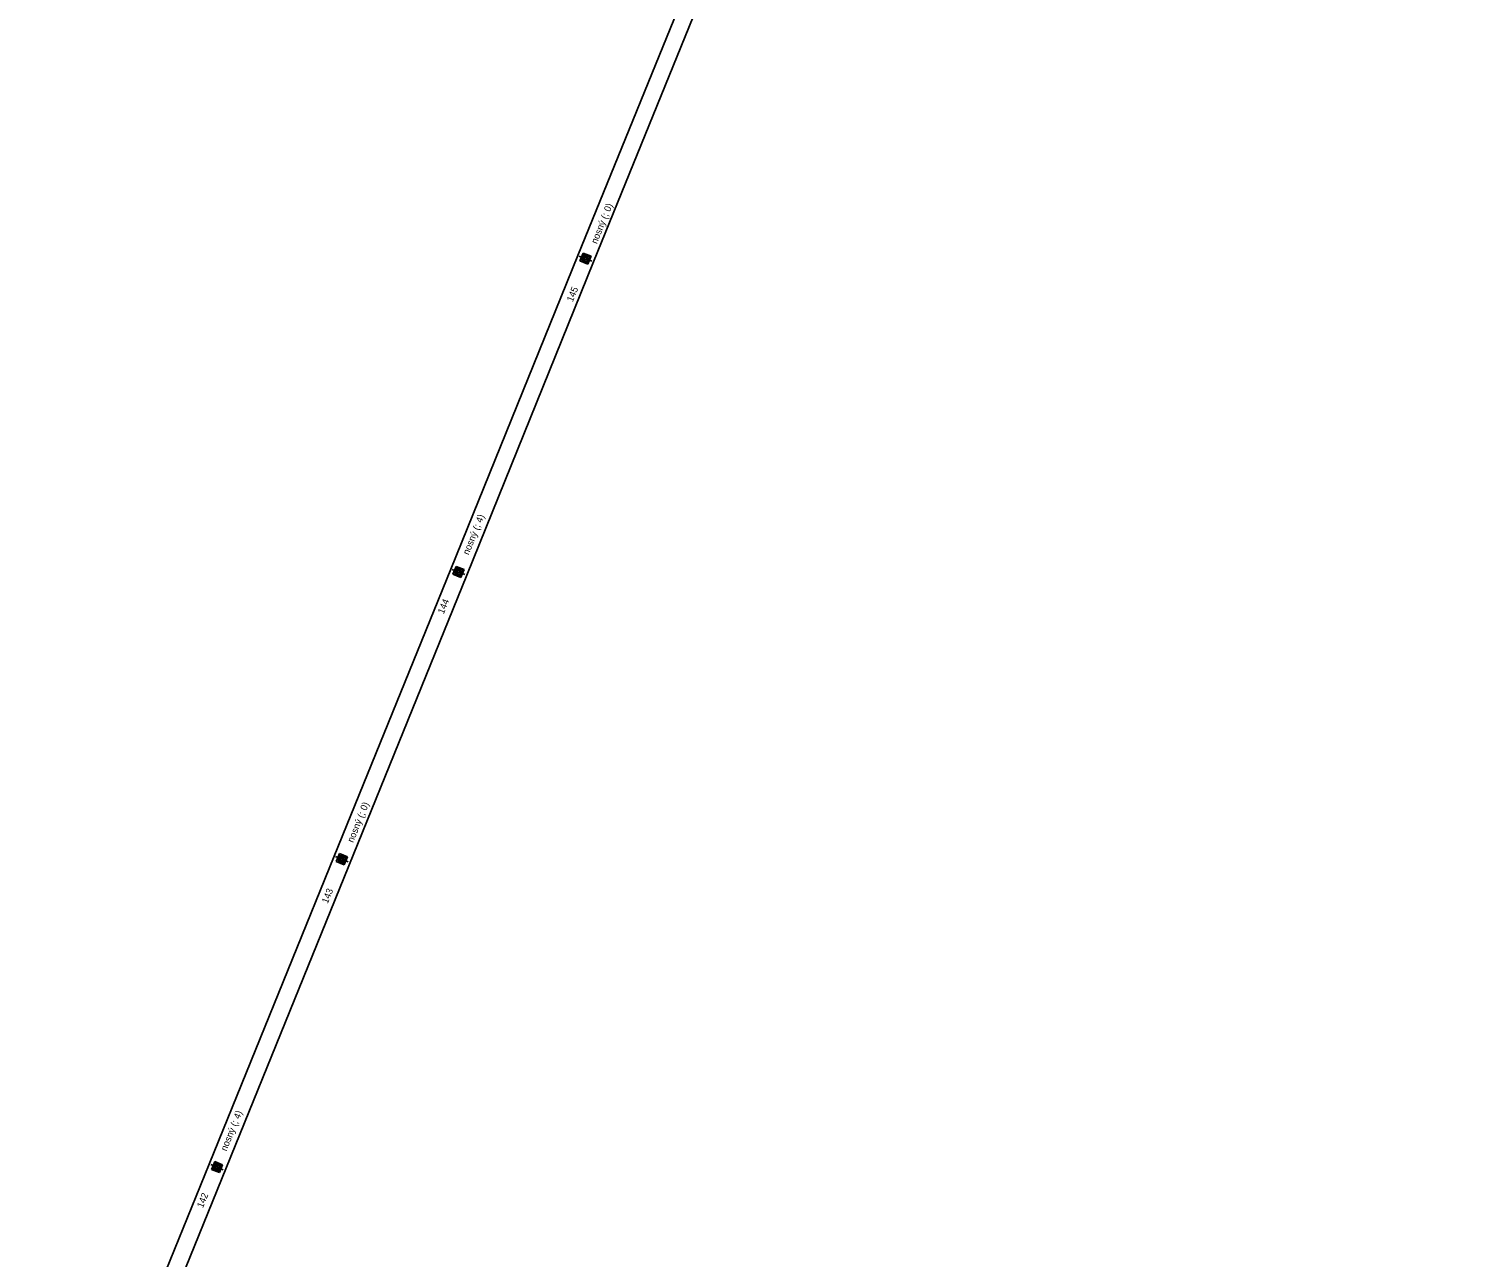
# Model space of a CAD drawing. Extents: x -745486 to -735508, y -1146235 to -1142575.
# Drawn here: x -737628 to -736558, y -1144416 to -1143504 of the extents above; entities that cross this region are included whole.
import ezdxf

# ---------------------------------------------------------------- set-up
doc = ezdxf.new("R2010")
doc.units = 0
for name, color, linetype in [('Vrstva 11', 7, 'Continuous'), ('Vrstva 12', 7, 'Continuous'), ('Vrstva 13', 7, 'Continuous'), ('Vrstva 3', 7, 'Continuous'), ('Vrstva 7', 7, 'Continuous')]:
    doc.layers.add(name, color=color, linetype=linetype)

# ---------------------------------------------------------------- blocks, each defined once
blk = doc.blocks.new('WN200')
at = {"layer": 'Vrstva 3'}
for points in [[(-6.3, 6.3), (6.3, 6.3)], [(-6.3, -6.3), (-6.3, 6.3)], [(-4.7, 4.6), (4.7, 4.6)], [(-4.7, -4.8), (-4.7, 4.6)], [(-3.1, 3.2), (3.1, 3.2)], [(-3.1, -3.2), (-3.1, 3.2)], [(-1.6, -1.4), (-1.6, 1.8)], [(-1.6, 1.8), (1.6, 1.8)], [(0, 6.3), (0, 10.1)], [(1.6, 1.8), (1.6, -1.4)], [(3.1, 3.2), (3.1, -3.2)], [(4.7, 4.6), (4.7, -4.8)], [(6.3, 6.3), (6.3, -6.3)], [(6.3, -6.3), (-6.3, -6.3)], [(4.7, -4.8), (-4.7, -4.8)], [(3.1, -3.2), (-3.1, -3.2)], [(1.6, -1.4), (-1.6, -1.4)], [(0, -6.3), (0, -10.1)]]:
    blk.add_lwpolyline(points, dxfattribs=at)

msp = doc.modelspace()

# ---------------------------------------------------------------- linework, layer by layer
at = {"layer": 'Vrstva 7'}
for points in [[(-738683, -1146233.5), (-738266.3, -1145695.6), (-738103.5, -1145486.1), (-737793.6, -1145085), (-737682.8, -1144811.5), (-737587, -1144576.1), (-737493.7, -1144346.4), (-737401, -1144118), (-737314.5, -1143904.9), (-737220.4, -1143672.3), (-737130.1, -1143450.5), (-737040.3, -1143228.4), (-736954.8, -1143011.1), (-736478.6, -1142863.7), (-735771.4, -1142646.3), (-735539.1, -1142574.5)], [(-738668.1, -1146234.5), (-738256.4, -1145703.4), (-738093.4, -1145494), (-737937.4, -1145291.7), (-737784.4, -1145095.6), (-737302.7, -1143909.4), (-737208.7, -1143677.1), (-737028.5, -1143233.5), (-736945, -1143021.3), (-736475.5, -1142875.9), (-735524.8, -1142583.3)]]:
    msp.add_lwpolyline(points, dxfattribs=at)

# ---------------------------------------------------------------- block references
at = {"layer": 'Vrstva 11', "xscale": 0.5000000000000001, "yscale": 0.4999999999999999, "rotation": 67.91249449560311}
for p in [(-737214.7, -1143674.6), (-737308.9, -1143907.1), (-737395.4, -1144120.2), (-737488, -1144348.7)]:
    msp.add_blockref('WN200', p, dxfattribs=at)

# ---------------------------------------------------------------- texts
at = {"layer": 'Vrstva 12'}
for s, p in [('145', (-737224.2, -1143707.1)), ('144', (-737319.9, -1143938.7)), ('143', (-737405.9, -1144153.5)), ('142', (-737498.5, -1144379.4))]:
    msp.add_text(s, height=5, rotation=67.912, dxfattribs=at).set_placement(p)
at = {"layer": 'Vrstva 13'}
for s, p in [('nosný (; 0)', (-737206.3, -1143664)), ('nosný (; 4)', (-737301.4, -1143894.8)), ('nosný (; 0)', (-737387, -1144108.3)), ('nosný (; 4)', (-737481, -1144337.2))]:
    msp.add_text(s, height=5, rotation=67.912, dxfattribs=at).set_placement(p)

doc.saveas('drawing.dxf')
